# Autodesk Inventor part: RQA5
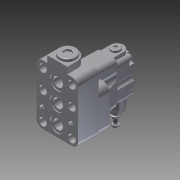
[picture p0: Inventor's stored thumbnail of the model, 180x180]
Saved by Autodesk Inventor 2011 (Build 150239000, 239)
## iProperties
Created: 2012-01
Part Number: RQA5
Document SubType Name: Modeling
Designer: khramov
Density: 1 g/cm^3
Author: khramov
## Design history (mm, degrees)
derived "RQA531.iam"
node "Твердое тело1"
node "0110215.ipt:1"
sketch "0112482.ipt:1"
sketch "0550326.ipt:1"
sketch "0112484.ipt:1"
sketch "0571501.ipt:1"
sketch "0119296.ipt:1"
sketch "0530544.ipt:1"
sketch "0530329_ISO_24017___M8x40.ipt:1"
sketch "0530083_UNI_5931___M10x45.ipt:1"
sketch "0530083_UNI_5931___M10x45.ipt:2"
sketch "0530083_UNI_5931___M10x45.ipt:3"
sketch "0530083_UNI_5931___M10x45.ipt:4"
node "0770690.ipt:1"
sketch "0550326_DIN_1481_6x16.ipt:1"
sketch "0550326_DIN_1481_6x16.ipt:2"
